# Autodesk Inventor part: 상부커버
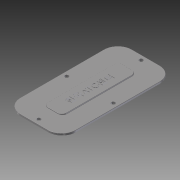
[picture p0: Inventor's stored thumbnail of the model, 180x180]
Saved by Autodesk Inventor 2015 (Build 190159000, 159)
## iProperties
Created: 2016-02
Part Number: 상부커버
Material: 강철, 연강
Document SubType Name: Modeling
Designer: mduedu
Density: 7.85 g/cm^3
Mass: 121.831 g
Surface Area: 149.263 cm^2
Volume: 15.5198 cm^3
Appearance: 반연마
Author: mduedu
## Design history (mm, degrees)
sketch "스케치1"
  geometry: L1 (30, 60)-(-30, 60); L2 (-30, 60)-(-30, -60); L3 (-30, -60)-(30, -60); L4 (30, -60)-(30, 60); L5 (30, 60)-(-30, -60); L6 (-30, 60)-(30, -60); 1 further point
  constraints: 12 end point, 2 midpoint, 2 parallel, 1 horizontal, 1 perpendicular
  dimensions: "d0" = 60 distance of L2.end L3.end; "d2" = 120 distance of L1.end L2.end
extrude "돌출1" new body sketch "스케치1" distance "d3" = 2; taper "d4" = 0 deg
fillet "모깎기1" dims "d5" = 15
sketch "스케치2"
  geometry: L1 (30, 45)-(30, -45) reference; L2 (15, -60)-(-15, -60) reference; L3 (-30, -45)-(-30, 45) reference; L4 (-15, 60)-(15, 60) reference; L5 (25, 45)-(25, -45); L6 (15, -55)-(-15, -55); L7 (-25, -45)-(-25, 45); L8 (-15, 55)-(15, 55); A1 r 15 centre (15, 45) between (30, 45) and (15, 60) reference; A2 r 15 centre (15, -45) between (15, -60) and (30, -45) reference; A3 r 15 centre (-15, -45) between (-30, -45) and (-15, -60) reference; A4 r 15 centre (-15, 45) between (-15, 60) and (-30, 45) reference; A5 r 10 centre (15, 45) between (25, 45) and (15, 55); A6 r 10 centre (15, -45) between (15, -55) and (25, -45); A7 r 10 centre (-15, -45) between (-25, -45) and (-15, -55); A8 r 10 centre (-15, 45) between (-15, 55) and (-25, 45); 4 further points
  constraints: 8 end point, 8 point on circle, 4 centre point, 4 midpoint, 7 other
  dimensions: "d8" = 5 distance between parallel lines of L7 L3
hole "구멍1" sketch "스케치2" at (0, 55), (25, 0), (0, -55), (-25, 0) diameter "d9" = 4; stored, may be unused: countersink angle "d13" = 90 deg, drill point angle "d15" = 118 deg; dims "d10" = 6, "d11" = 4, "d12" = 2, "d14" = 8
sketch "스케치3"
  geometry: L1 (10, -40)-(-10, -40); L2 (-10, -40)-(-10, 40); L3 (-10, 40)-(10, 40); L4 (10, 40)-(10, -40); L5 (10, -40)-(-10, 40); L6 (-10, -40)-(10, 40); 1 further point
  constraints: 12 end point, 2 midpoint, 2 parallel, 1 horizontal, 1 perpendicular
  dimensions: "d16" = 80 distance of L1.end L2.end; "d18" = 20 distance of L2.end L3.end
extrude "돌출2" join sketch "스케치3" distance "d19" = 1; taper "d20" = 0 deg
fillet "모깎기2" dims "d21" = 5
fillet "모깎기3" dims "d22" = 0.3
fillet "모깎기4" dims "d23" = 0.3
sketch "스케치4"
  geometry: 2 further points
  constraints: 1 coincident, 1 other
feature "엠보싱1" sketch "스케치4" dims "d0" = 60, "d2" = 120, "d8" = 5, "d24" = 0.5, "d25" = 0
node "솔리드1"
node "절단 모서리 투영1"
